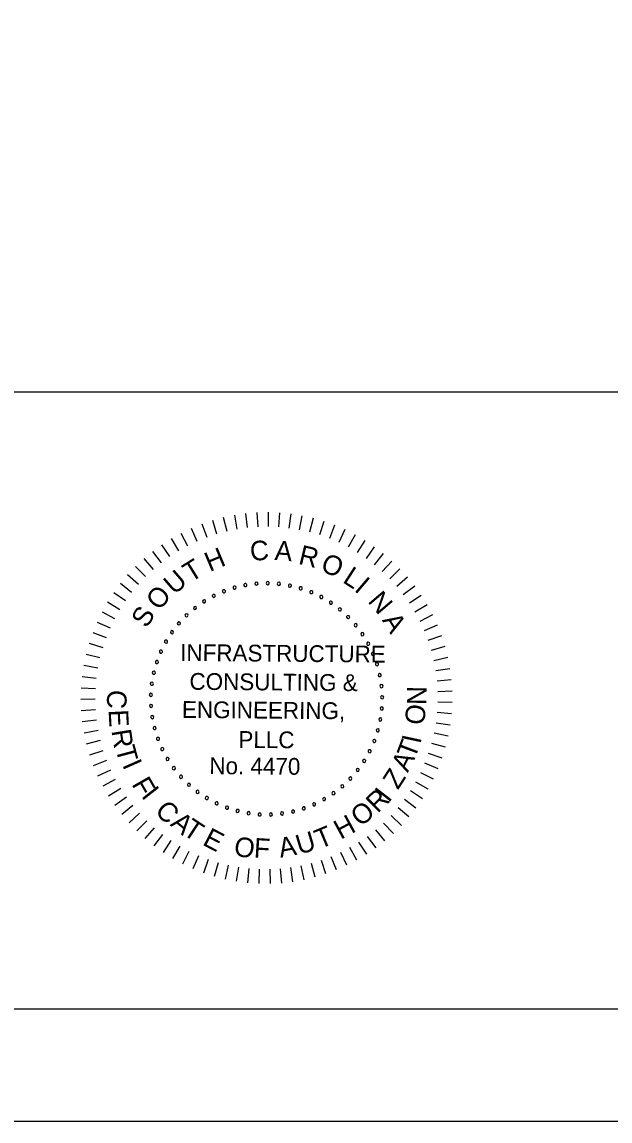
# Model space of a CAD drawing. Extents: x -133.1 to -97, y -1.7 to 20.3.
# Drawn here: x -107.898 to -105.277, y -1.691 to 3.208 of the extents above; entities that cross this region are included whole.
import ezdxf

# ---------------------------------------------------------------- set-up
doc = ezdxf.new("R2010")
doc.units = 0
for name, color, linetype in [('BR_BORDER LINES', 7, 'Continuous'), ('BR_TEXT', 7, 'Continuous'), ('Level 31', 7, 'Continuous')]:
    doc.layers.add(name, color=color, linetype=linetype)

msp = doc.modelspace()

# ---------------------------------------------------------------- linework, layer by layer
at = {"layer": 'BR_BORDER LINES'}
for p, q in [((-110.5071, 1.5591), (-105.1419, 1.5591)), ((-131.3076, -1.191), (-97.6416, -1.191))]:
    msp.add_line(p, q, dxfattribs=at)
at = {"layer": 'BR_TEXT'}
for p, q in [((-107.0494, 0.9866), (-107.0308, 0.9257)), ((-107.0007, 0.9998), (-106.9858, 0.9379)), ((-106.9512, 1.01), (-106.9401, 0.9473)), ((-106.9012, 1.0172), (-106.894, 0.9539)), ((-106.8509, 1.0213), (-106.8476, 0.9578)), ((-106.8005, 1.0224), (-106.801, 0.9587)), ((-106.75, 1.0204), (-106.7544, 0.9569)), ((-106.6998, 1.0153), (-106.7081, 0.9522)), ((-106.65, 1.0071), (-106.6621, 0.9446)), ((-106.6007, 0.996), (-106.6166, 0.9343)), ((-106.5523, 0.9818), (-106.5719, 0.9213)), ((-107.1439, 0.9513), (-107.1181, 0.8932)), ((-107.0972, 0.9704), (-107.0749, 0.9107)), ((-106.5048, 0.9648), (-106.528, 0.9055)), ((-106.4584, 0.9448), (-106.4852, 0.8871)), ((-107.2335, 0.9049), (-107.2008, 0.8503)), ((-107.1895, 0.9295), (-107.1601, 0.873)), ((-106.4133, 0.9221), (-106.4436, 0.8661)), ((-106.3697, 0.8967), (-106.4034, 0.8426)), ((-107.3168, 0.8478), (-107.2776, 0.7976)), ((-107.276, 0.8776), (-107.24, 0.8251)), ((-106.3277, 0.8686), (-106.3646, 0.8167)), ((-106.2875, 0.8381), (-106.3275, 0.7885)), ((-107.3557, 0.8156), (-107.3135, 0.7679)), ((-106.2493, 0.8051), (-106.2922, 0.7581)), ((-107.4272, 0.7444), (-107.3795, 0.7022)), ((-107.3925, 0.7811), (-107.3475, 0.736)), ((-106.2131, 0.7699), (-106.2588, 0.7256)), ((-107.4595, 0.7056), (-107.4094, 0.6664)), ((-106.1791, 0.7326), (-106.2275, 0.6911)), ((-106.1475, 0.6932), (-106.1983, 0.6548)), ((-107.4895, 0.665), (-107.437, 0.6289)), ((-106.1184, 0.652), (-106.1714, 0.6167)), ((-107.5169, 0.6226), (-107.4623, 0.5897)), ((-106.0918, 0.6091), (-106.1469, 0.5771)), ((-107.5416, 0.5786), (-107.4852, 0.5491)), ((-106.0679, 0.5646), (-106.1248, 0.5361)), ((-107.5637, 0.5332), (-107.5055, 0.5072)), ((-106.0467, 0.5188), (-106.1052, 0.4938)), ((-107.5829, 0.4865), (-107.5233, 0.4641)), ((-106.0283, 0.4718), (-106.0883, 0.4504)), ((-107.5992, 0.4387), (-107.5384, 0.42)), ((-106.0129, 0.4237), (-106.0741, 0.406)), ((-107.6126, 0.3901), (-107.5507, 0.3751)), ((-106.0004, 0.3748), (-106.0625, 0.3608)), ((-107.623, 0.3407), (-107.5604, 0.3295)), ((-105.9909, 0.3252), (-106.0538, 0.3151)), ((-107.6304, 0.2907), (-107.5672, 0.2834)), ((-105.9845, 0.2751), (-106.0479, 0.2689)), ((-107.6348, 0.2404), (-107.5712, 0.237)), ((-105.9811, 0.2247), (-106.0448, 0.2224)), ((-107.636, 0.19), (-107.5723, 0.1904)), ((-105.9809, 0.1743), (-106.0445, 0.1758)), ((-107.6342, 0.1395), (-107.5706, 0.1438)), ((-105.9836, 0.1239), (-106.0471, 0.1292)), ((-107.6293, 0.0893), (-107.5661, 0.0974)), ((-107.6213, 0.0394), (-107.5588, 0.0514)), ((-105.9895, 0.0737), (-106.0525, 0.0829)), ((-107.6103, -0.0099), (-107.5487, 0.0059)), ((-105.9984, 0.024), (-106.0607, 0.0371)), ((-107.5964, -0.0584), (-107.5358, -0.0388)), ((-106.0103, -0.025), (-106.0717, -0.0082)), ((-107.5795, -0.106), (-107.5202, -0.0828)), ((-106.043, -0.1205), (-106.1019, -0.0963)), ((-106.0252, -0.0733), (-106.0855, -0.0527)), ((-107.5597, -0.1524), (-107.5019, -0.1256)), ((-106.0636, -0.1666), (-106.1209, -0.1389)), ((-107.5371, -0.1976), (-107.4811, -0.1673)), ((-106.087, -0.2113), (-106.1426, -0.1802)), ((-107.5119, -0.2413), (-107.4578, -0.2077)), ((-106.1131, -0.2545), (-106.1667, -0.22)), ((-107.484, -0.2834), (-107.4321, -0.2465)), ((-107.4536, -0.3237), (-107.404, -0.2837)), ((-106.1418, -0.2961), (-106.1931, -0.2584)), ((-107.4208, -0.362), (-107.3737, -0.3191)), ((-106.2065, -0.3735), (-106.2529, -0.3299)), ((-106.173, -0.3358), (-106.2219, -0.2951)), ((-107.3857, -0.3983), (-107.3413, -0.3527)), ((-107.3485, -0.4324), (-107.307, -0.3841)), ((-106.2423, -0.4092), (-106.2859, -0.3628)), ((-107.3092, -0.4642), (-107.2708, -0.4135)), ((-107.2681, -0.4935), (-107.2328, -0.4405)), ((-106.32, -0.4736), (-106.3576, -0.4222)), ((-106.2801, -0.4426), (-106.3208, -0.3936)), ((-107.2253, -0.5203), (-107.1933, -0.4652)), ((-107.1809, -0.5444), (-107.1523, -0.4875)), ((-106.4049, -0.528), (-106.436, -0.4725)), ((-106.3616, -0.5021), (-106.3961, -0.4485)), ((-107.1352, -0.5657), (-107.1101, -0.5072)), ((-107.0882, -0.5842), (-107.0668, -0.5243)), ((-107.0402, -0.5998), (-107.0225, -0.5387)), ((-106.5432, -0.5894), (-106.5637, -0.5291)), ((-106.4959, -0.5718), (-106.52, -0.5128)), ((-106.4498, -0.5513), (-106.4774, -0.4939)), ((-106.9913, -0.6125), (-106.9773, -0.5504)), ((-106.9418, -0.6221), (-106.9316, -0.5593)), ((-106.8918, -0.6288), (-106.8854, -0.5654)), ((-106.8414, -0.6323), (-106.8389, -0.5687)), ((-106.7909, -0.6328), (-106.7923, -0.5691)), ((-106.7405, -0.6302), (-106.7458, -0.5667)), ((-106.6903, -0.6245), (-106.6995, -0.5615)), ((-106.6406, -0.6158), (-106.6536, -0.5535)), ((-106.5915, -0.6041), (-106.6083, -0.5427))]:
    msp.add_line(p, q, dxfattribs=at)
for centre, start, end in [((-106.9506, 0.6862), 16.1422, 196.1422), ((-106.9506, 0.6862), 196.1422, 16.1422), ((-106.9021, 0.6977), 10.6038, 190.6038), ((-106.9021, 0.6977), 190.6038, 10.6038), ((-106.8527, 0.7043), 5.0653, 185.0653), ((-106.8527, 0.7043), 185.0653, 5.0653), ((-106.8029, 0.7062), 359.5268, 179.5268), ((-106.8029, 0.7062), 179.5268, 359.5268), ((-106.7531, 0.7033), 173.9884, 353.9884), ((-106.7531, 0.7033), 353.9884, 173.9884), ((-106.7039, 0.6956), 168.4499, 348.4499), ((-106.7039, 0.6956), 348.4499, 168.4499), ((-106.6557, 0.6832), 342.9114, 162.9114), ((-107.0431, 0.6496), 27.2191, 207.2191), ((-107.0431, 0.6496), 207.2191, 27.2191), ((-106.9977, 0.6702), 21.6807, 201.6807), ((-106.9977, 0.6702), 201.6807, 21.6807), ((-106.6557, 0.6832), 162.9114, 342.9114), ((-106.6088, 0.6662), 157.373, 337.373), ((-106.6088, 0.6662), 337.373, 157.373), ((-106.5639, 0.6447), 151.8345, 331.8345), ((-106.5639, 0.6447), 331.8345, 151.8345), ((-107.127, 0.5959), 38.2961, 218.2961), ((-107.127, 0.5959), 218.2961, 38.2961), ((-107.0864, 0.6248), 32.7576, 212.7576), ((-107.0864, 0.6248), 212.7576, 32.7576), ((-106.5212, 0.619), 146.2961, 326.2961), ((-106.5212, 0.619), 326.2961, 146.2961), ((-106.4811, 0.5893), 140.7576, 320.7576), ((-106.4811, 0.5893), 320.7576, 140.7576), ((-107.1646, 0.5633), 43.8345, 223.8345), ((-107.1646, 0.5633), 223.8345, 43.8345), ((-106.4442, 0.5559), 135.2191, 315.2191), ((-106.4442, 0.5559), 315.2191, 135.2191), ((-107.2296, 0.4879), 54.9114, 234.9114), ((-107.2296, 0.4879), 234.9114, 54.9114), ((-107.1989, 0.5271), 49.373, 229.373), ((-107.1989, 0.5271), 229.373, 49.373), ((-106.4106, 0.5191), 129.6807, 309.6807), ((-106.4106, 0.5191), 309.6807, 129.6807), ((-107.2563, 0.4458), 60.4499, 240.4499), ((-107.2563, 0.4458), 240.4499, 60.4499), ((-106.3808, 0.4792), 124.1422, 304.1422), ((-106.3808, 0.4792), 304.1422, 124.1422), ((-106.3549, 0.4366), 118.6038, 298.6038), ((-106.3549, 0.4366), 298.6038, 118.6038), ((-107.2788, 0.4014), 65.9884, 245.9884), ((-107.2788, 0.4014), 245.9884, 65.9884), ((-106.3333, 0.3917), 113.0653, 293.0653), ((-106.3333, 0.3917), 293.0653, 113.0653), ((-107.297, 0.3549), 71.5268, 251.5268), ((-107.297, 0.3549), 251.5268, 71.5268), ((-106.3161, 0.3449), 107.5268, 287.5268), ((-106.3161, 0.3449), 287.5268, 107.5268), ((-107.3106, 0.307), 77.0653, 257.0653), ((-107.3106, 0.307), 257.0653, 77.0653), ((-106.3035, 0.2967), 101.9884, 281.9884), ((-106.3035, 0.2967), 281.9884, 101.9884), ((-107.3195, 0.258), 82.6038, 262.6038), ((-107.3195, 0.258), 262.6038, 82.6038), ((-106.2956, 0.2475), 96.4499, 276.4499), ((-106.2956, 0.2475), 276.4499, 96.4499), ((-107.3236, 0.2083), 88.1422, 268.1422), ((-107.3236, 0.2083), 268.1422, 88.1422), ((-106.2925, 0.1977), 90.9114, 270.9114), ((-106.2925, 0.1977), 270.9114, 90.9114), ((-107.3229, 0.1585), 93.6807, 273.6807), ((-107.3229, 0.1585), 273.6807, 93.6807), ((-106.2942, 0.1479), 85.373, 265.373), ((-106.2942, 0.1479), 265.373, 85.373), ((-107.3174, 0.109), 99.2191, 279.2191), ((-107.3174, 0.109), 279.2191, 99.2191), ((-106.3007, 0.0985), 79.8345, 259.8345), ((-106.3007, 0.0985), 259.8345, 79.8345), ((-107.3071, 0.0602), 104.7576, 284.7576), ((-107.3071, 0.0602), 284.7576, 104.7576), ((-106.312, 0.05), 74.2961, 254.2961), ((-106.312, 0.05), 254.2961, 74.2961), ((-107.2922, 0.0126), 110.2961, 290.2961), ((-107.2922, 0.0126), 290.2961, 110.2961), ((-106.3279, 0.0028), 68.7576, 248.7576), ((-106.3279, 0.0028), 248.7576, 68.7576), ((-107.2728, -0.0332), 115.8345, 295.8345), ((-107.2728, -0.0332), 295.8345, 115.8345), ((-106.3483, -0.0427), 63.2191, 243.2191), ((-106.3483, -0.0427), 243.2191, 63.2191), ((-107.249, -0.077), 121.373, 301.373), ((-107.249, -0.077), 301.373, 121.373), ((-106.3729, -0.086), 57.6807, 237.6807), ((-106.3729, -0.086), 237.6807, 57.6807), ((-107.2211, -0.1183), 126.9114, 306.9114), ((-107.2211, -0.1183), 306.9114, 126.9114), ((-106.4016, -0.1267), 52.1422, 232.1422), ((-106.4016, -0.1267), 232.1422, 52.1422), ((-107.1894, -0.1567), 132.4499, 312.4499), ((-107.1894, -0.1567), 312.4499, 132.4499), ((-107.1541, -0.1919), 137.9884, 317.9884), ((-107.1541, -0.1919), 317.9884, 137.9884), ((-106.4702, -0.1989), 41.0653, 221.0653), ((-106.4702, -0.1989), 221.0653, 41.0653), ((-106.4342, -0.1645), 46.6038, 226.6038), ((-106.4342, -0.1645), 226.6038, 46.6038), ((-107.1156, -0.2235), 143.5268, 323.5268), ((-107.1156, -0.2235), 323.5268, 143.5268), ((-107.0742, -0.2512), 329.0653, 149.0653), ((-106.5093, -0.2297), 35.5268, 215.5268), ((-106.5093, -0.2297), 215.5268, 35.5268), ((-107.0742, -0.2512), 149.0653, 329.0653), ((-107.0303, -0.2749), 154.6038, 334.6038), ((-107.0303, -0.2749), 334.6038, 154.6038), ((-106.9843, -0.2941), 160.1422, 340.1422), ((-106.9843, -0.2941), 340.1422, 160.1422), ((-106.642, -0.2976), 18.9114, 198.9114), ((-106.5957, -0.2793), 24.4499, 204.4499), ((-106.5957, -0.2793), 204.4499, 24.4499), ((-106.5513, -0.2566), 29.9884, 209.9884), ((-106.5513, -0.2566), 209.9884, 29.9884), ((-106.9367, -0.3089), 165.6807, 345.6807), ((-106.9367, -0.3089), 345.6807, 165.6807), ((-106.8879, -0.3189), 171.2191, 351.2191), ((-106.8879, -0.3189), 351.2191, 171.2191), ((-106.8384, -0.3242), 356.7576, 176.7576), ((-106.8384, -0.3242), 176.7576, 356.7576), ((-106.7885, -0.3248), 2.2961, 182.2961), ((-106.7885, -0.3248), 182.2961, 2.2961), ((-106.7389, -0.3205), 7.8345, 187.8345), ((-106.7389, -0.3205), 187.8345, 7.8345), ((-106.6899, -0.3114), 13.373, 193.373), ((-106.6899, -0.3114), 193.373, 13.373), ((-106.642, -0.2976), 198.9114, 18.9114)]:
    msp.add_arc(centre, 0.00701, start, end, dxfattribs=at)
at = {"layer": 'Level 31'}
msp.add_lwpolyline([(-133.1409, -1.691), (-97.141, -1.691), (-97.141, 20.309), (-133.1409, 20.309)], close=True, dxfattribs=at)

# ---------------------------------------------------------------- texts
at = {"layer": 'BR_TEXT'}
for s, height, rotation, p in [('C', 0.0872, 4.7281, (-106.8784, 0.8048)), ('A', 0.0872, 355.6981, (-106.7739, 0.8098)), ('H', 0.0872, 22.7882, (-107.0612, 0.7554)), ('R', 0.0872, 346.6681, (-106.6696, 0.7928)), ('O', 0.0872, 337.638, (-106.5719, 0.763)), ('T', 0.0872, 31.8182, (-107.1461, 0.7078)), ('U', 0.0872, 40.8482, (-107.2194, 0.6516)), ('L', 0.0872, 327.108, (-106.4731, 0.7125)), ('O', 0.0872, 49.8782, (-107.2864, 0.5806)), ('I', 0.0872, 319.578, (-106.4205, 0.6747)), ('N', 0.0872, 310.548, (-106.3597, 0.6239)), ('S', 0.0872, 58.9083, (-107.3418, 0.5024)), ('A', 0.0872, 301.5179, (-106.2946, 0.5415)), ('INFRASTRUCTURE', 0.074771, 359.5268, (-107.1932, 0.3599)), ('CONSULTING &', 0.074771, 359.5268, (-107.1519, 0.2313)), ('C', 0.0872, 267.025, (-107.5168, 0.2325)), ('N', 0.0872, 89.2085, (-106.0953, 0.1628)), ('ENGINEERING,', 0.074771, 359.5268, (-107.1855, 0.1059)), ('O', 0.0872, 83.2085, (-106.1064, 0.0713)), ('E', 0.0872, 273.025, (-107.5124, 0.1409)), ('R', 0.0872, 279.025, (-107.4996, 0.0487)), ('PLLC', 0.07477, 359.5268, (-106.9338, -0.0277)), ('T', 0.0872, 69.3954, (-106.1476, -0.0805)), ('I', 0.0872, 77.9093, (-106.1219, -0.013)), ('T', 0.0872, 285.025, (-107.4822, -0.0301)), ('I', 0.0872, 293.7713, (-107.4525, -0.1032)), ('No. 4470', 0.07477, 359.5268, (-107.0633, -0.1446)), ('A', 0.0872, 63.3954, (-106.1784, -0.1408)), ('Z', 0.0872, 57.3954, (-106.2222, -0.2172)), ('F', 0.0872, 299.7713, (-107.4113, -0.1893)), ('I', 0.0872, 308.5268, (-107.3692, -0.2431)), ('R', 0.0872, 44.5268, (-106.3127, -0.3221)), ('I', 0.0872, 52.3339, (-106.2633, -0.2748)), ('C', 0.0872, 314.5268, (-107.3099, -0.3133)), ('O', 0.0872, 38.5268, (-106.3893, -0.3821)), ('A', 0.0872, 320.5268, (-107.2407, -0.3718)), ('T', 0.0872, 326.5268, (-107.1863, -0.4103)), ('H', 0.0872, 28.5268, (-106.4774, -0.4381)), ('E', 0.0872, 332.5268, (-107.0977, -0.4581)), ('T', 0.0872, 22.5268, (-106.5706, -0.4799)), ('O', 0.0872, 350.5268, (-106.9576, -0.507)), ('F', 0.0872, 356.5268, (-106.8661, -0.5161)), ('A', 0.0872, 10.5268, (-106.7462, -0.5177)), ('U', 0.0872, 16.5268, (-106.6623, -0.5042))]:
    msp.add_text(s, height=height, rotation=rotation, dxfattribs=at).set_placement(p)

doc.saveas('drawing.dxf')
